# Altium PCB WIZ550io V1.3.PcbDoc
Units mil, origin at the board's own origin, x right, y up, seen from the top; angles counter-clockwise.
Board outline 2165.35 x 1023.62 mil, 4 copper layers (Top Layer, Internal Plane 1, Internal Plane 2, Bottom Layer); 65 components, 50 nets, 220 pads, 114 vias.
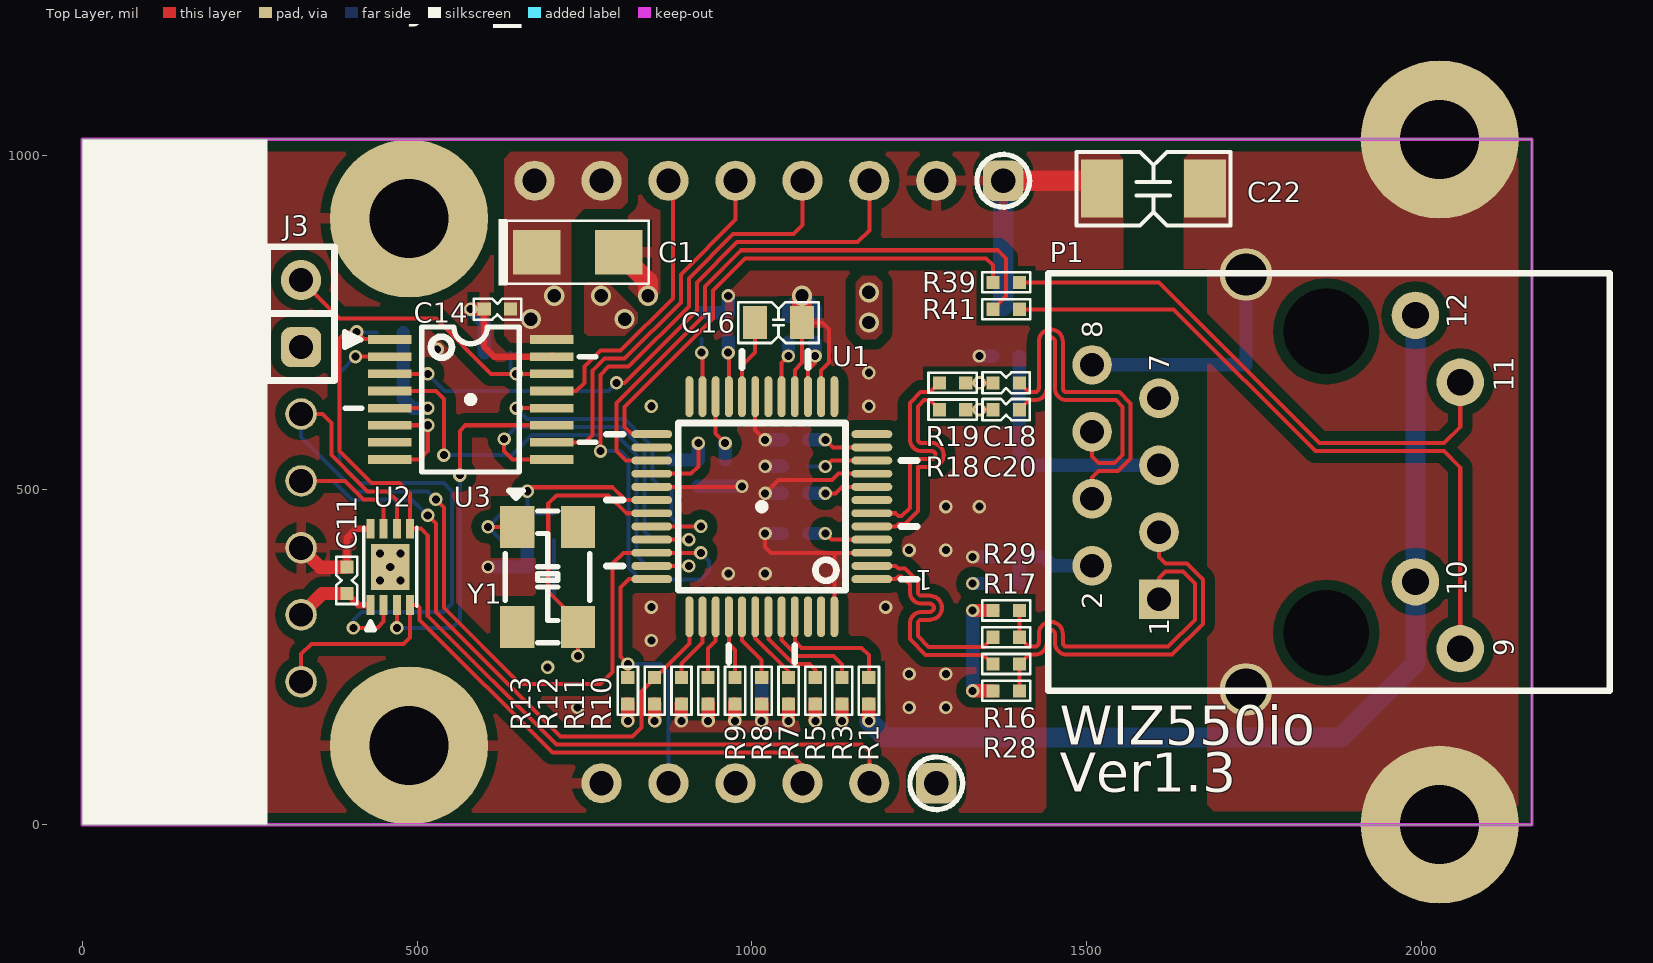
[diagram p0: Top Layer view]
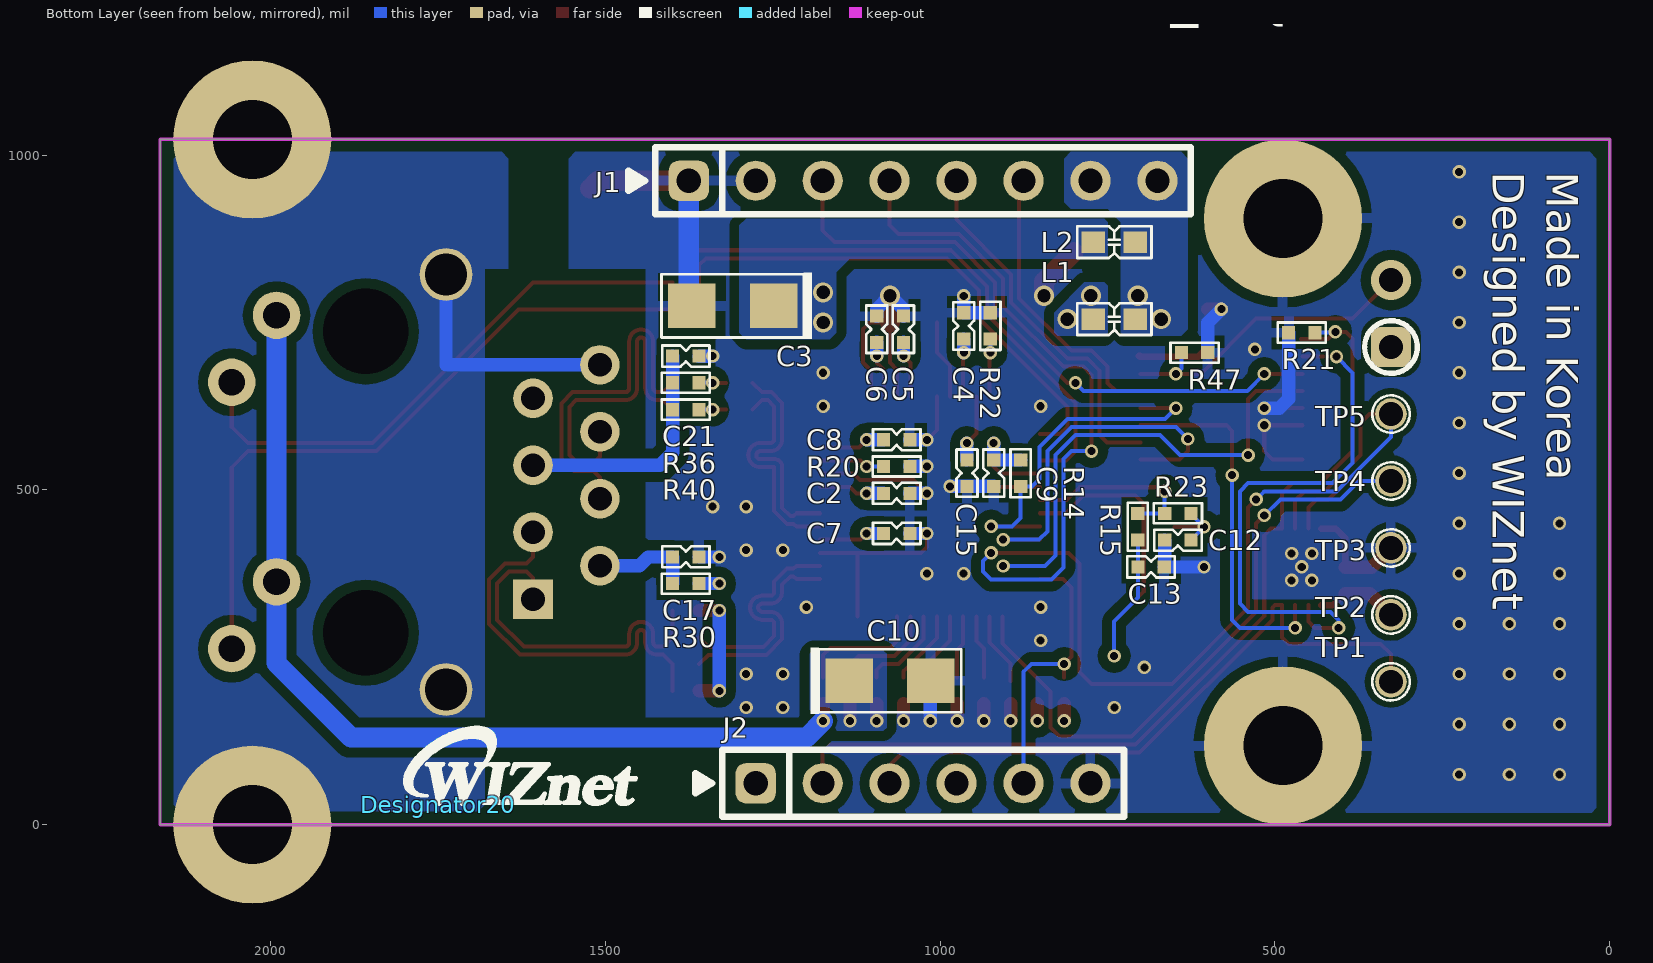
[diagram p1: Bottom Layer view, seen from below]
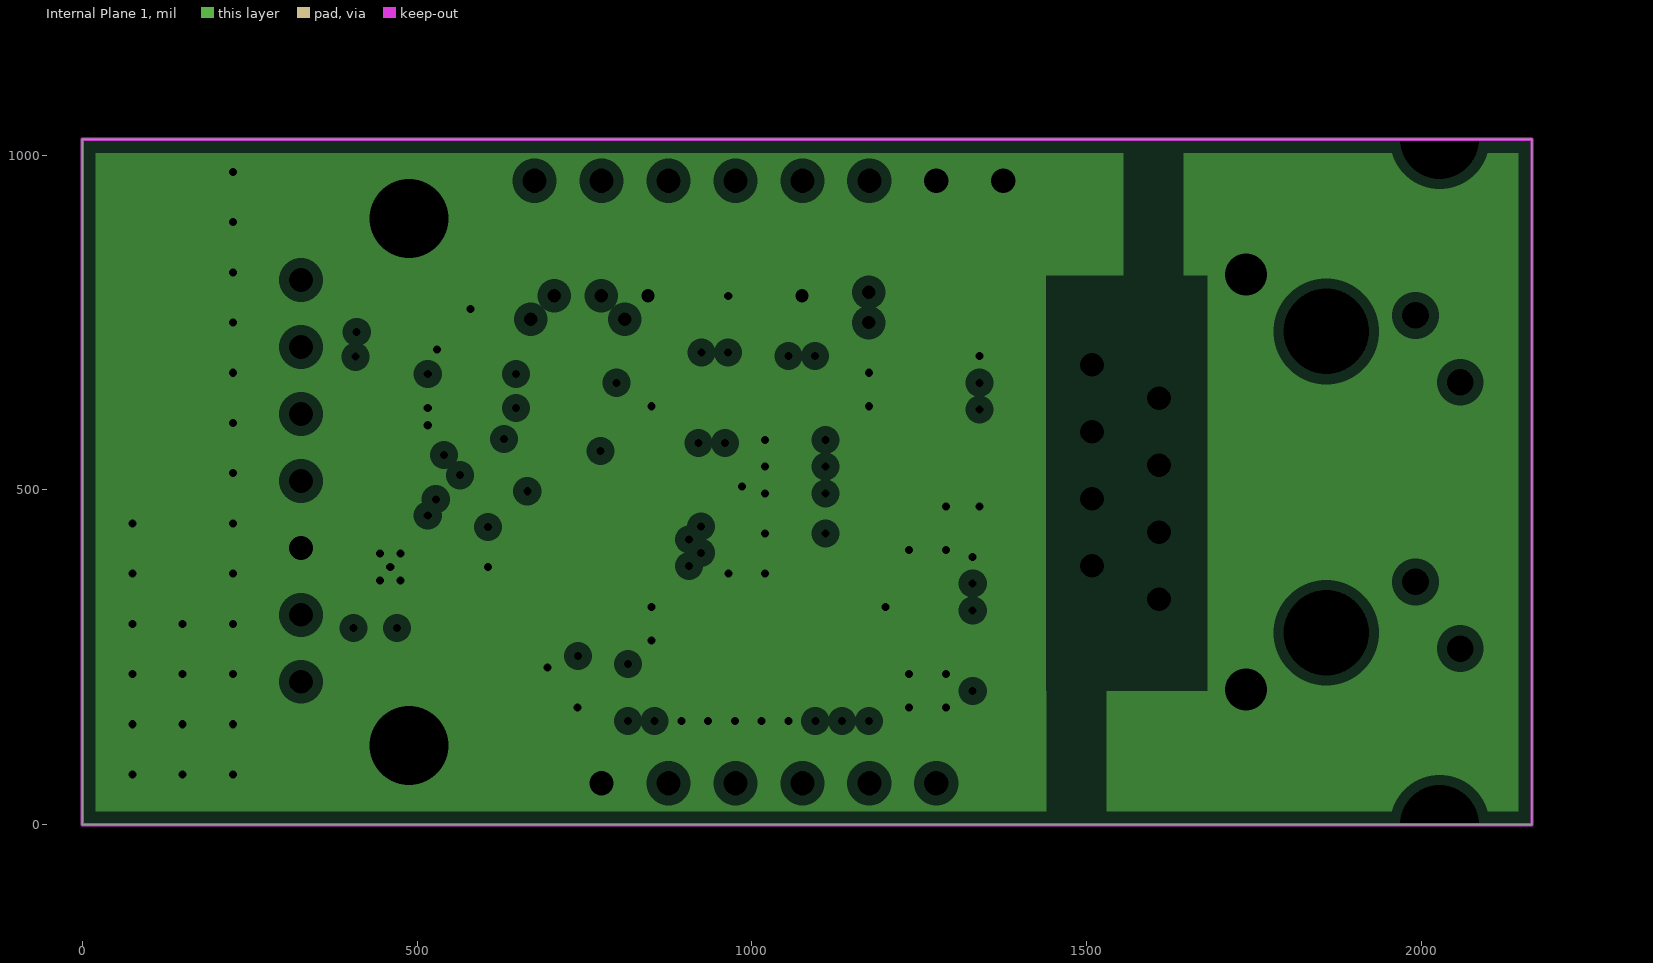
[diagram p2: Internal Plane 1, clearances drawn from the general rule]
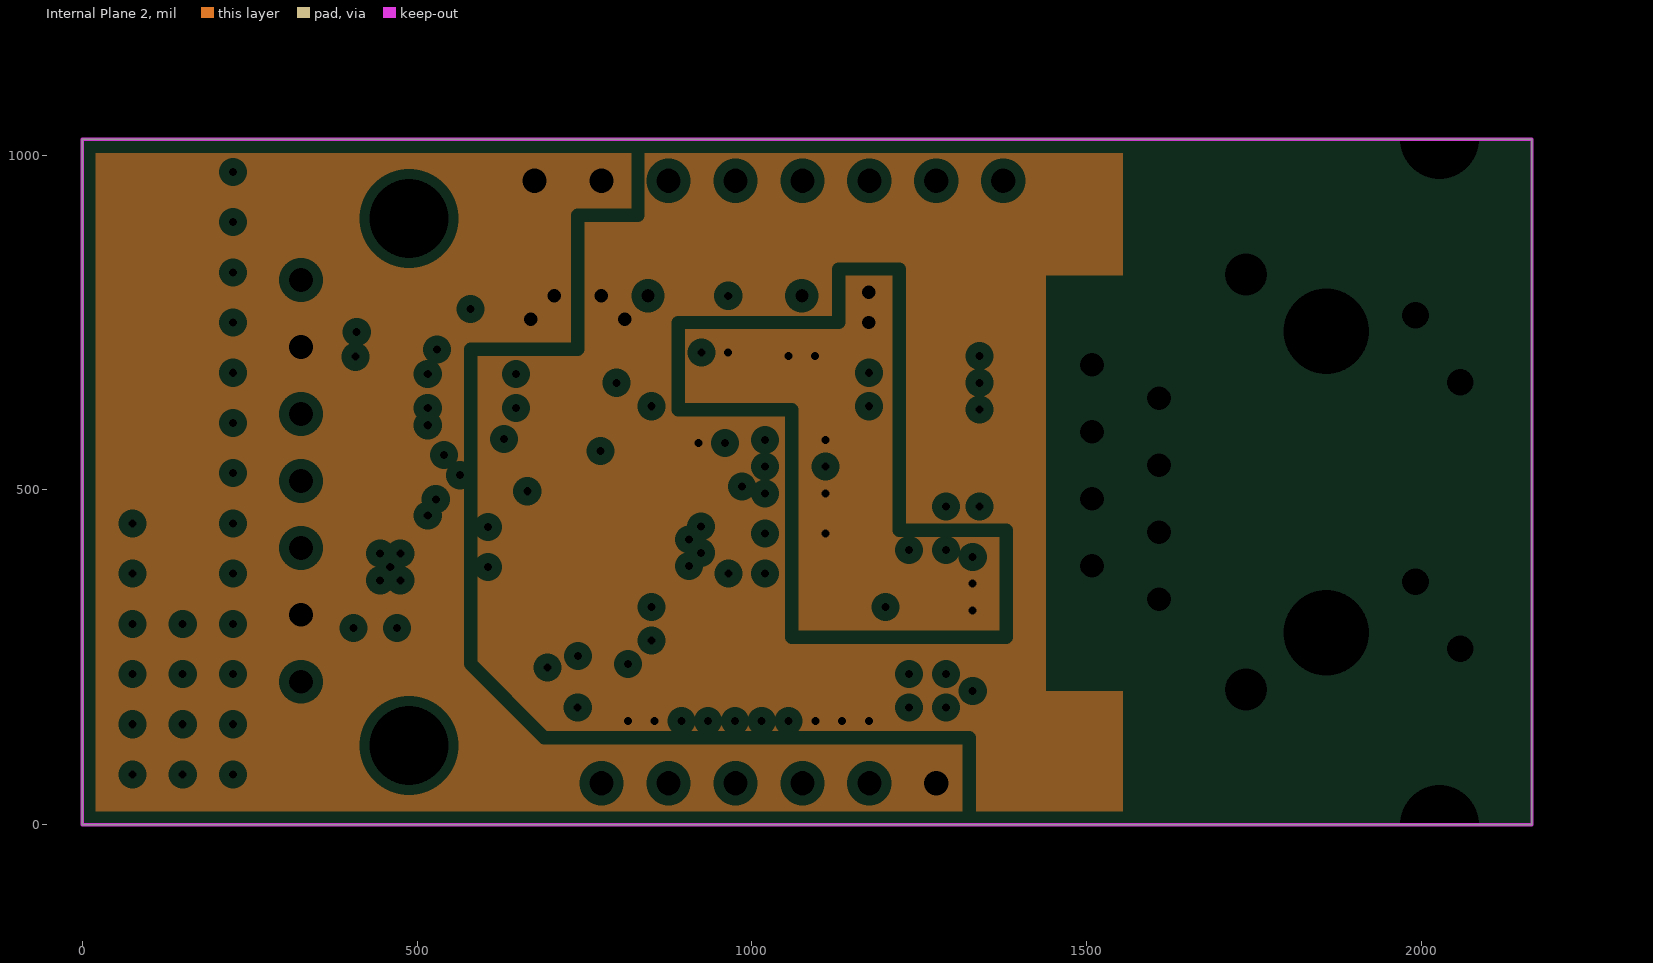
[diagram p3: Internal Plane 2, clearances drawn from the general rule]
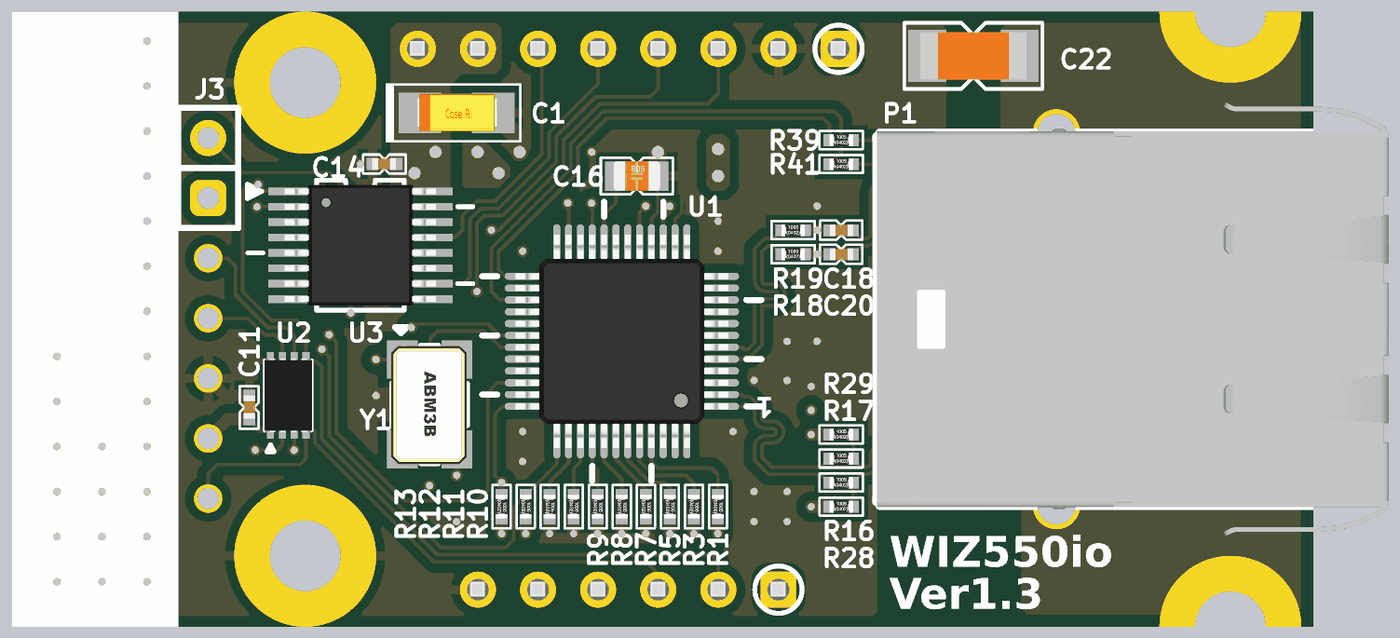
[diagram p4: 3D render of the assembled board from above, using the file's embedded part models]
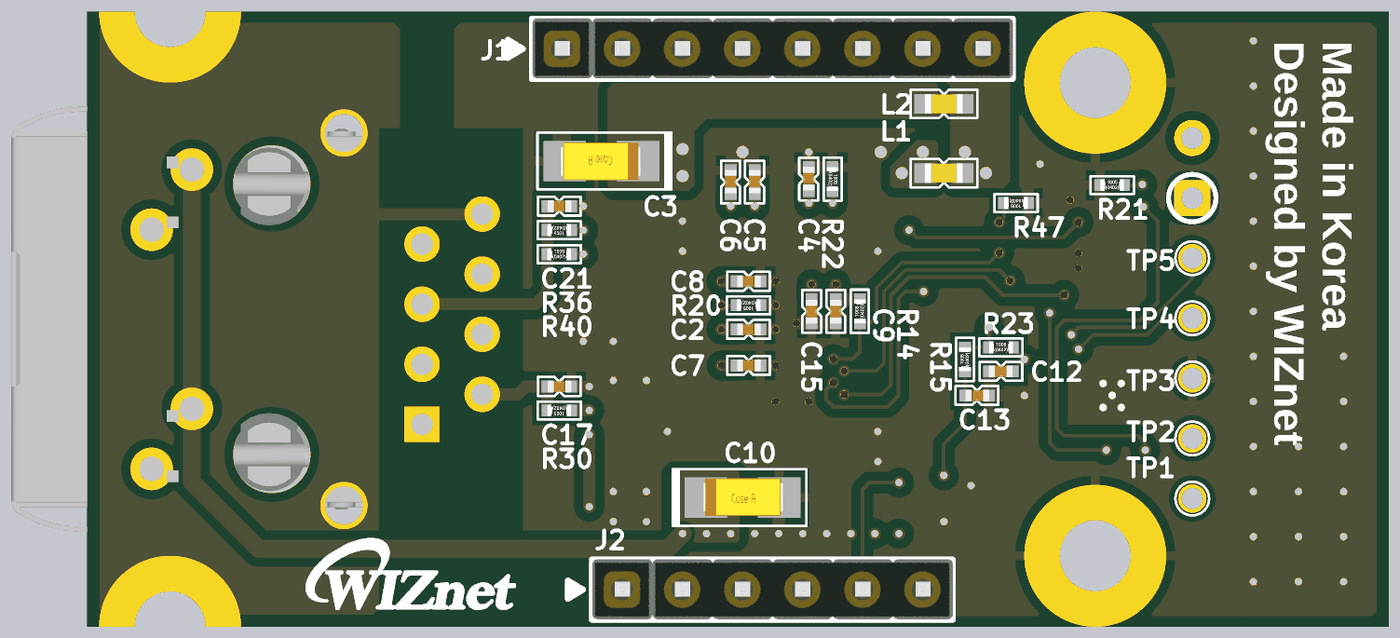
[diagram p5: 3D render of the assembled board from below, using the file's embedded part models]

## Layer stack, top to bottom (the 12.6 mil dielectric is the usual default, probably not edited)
Top Solder: solder mask 0.4, Solder Resist, Dk 3.5
Top Layer: signal copper 1.4
Dielectric1: core 12.6, FR-4, Dk 4.8
Internal Plane 1: plane copper 1.4
Dielectric5: prepreg 12.6, FR-4, Dk 4.8
Internal Plane 2: plane copper 1.4
Dielectric6: core 12.6, FR-4, Dk 4.8
Bottom Layer: signal copper 1.4
Bottom Solder: solder mask 0.4, Solder Resist, Dk 3.5

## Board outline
0,0 2165.35,0 2165.35,1023.62 0,1023.62

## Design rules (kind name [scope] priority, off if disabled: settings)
Clearance [All] p1: gap=6
DiffPairsRouting [All] p1: maxlimit=10 minlimit=5 mostfreqgap=6 toplayer_minwidth=15 toplayer_maxwidth=15 toplayer_prefwidth=15 bottomlayer_minwidth=15 bottomlayer_maxwidth=15 bottomlayer_prefwidth=15 maxuncoupledlength=500
HoleSize [All] p1: absolutevalues=TRUE maxlimit=160 minlimit=1 maxpercent=80.000 minpercent=20.000
PlaneClearance [All] p1: clearance=15
PlaneConnect [All] p1: planeconnectstyle=Direct reliefexpansion=20 reliefentries=4 reliefconductorwidth=10 reliefairgap=10
PolygonConnect PolygonConnect_2 [IsPad vs IsNamedPolygon('Top Layer-GND') Or  IsNamedPolygon('Bottom Layer-GND')] p1: connectstyle=Relief reliefconductorwidth=15 reliefentries=4 polygonreliefangle="90 Angle" airgapwidth=15
PolygonConnect PolygonConnect_1 [IsVia] p2: connectstyle=Direct reliefconductorwidth=10 reliefentries=4 polygonreliefangle="90 Angle" airgapwidth=10
PolygonConnect [All] p3: connectstyle=Direct reliefconductorwidth=10 reliefentries=4 polygonreliefangle="90 Angle" airgapwidth=10
RoutingVias [All] p1: holewidth=12 width=20 viastyle="Through Hole" minholewidth=12 minwidth=20 maxholewidth=20 maxwidth=30
SolderMaskExpansion [All] p1: expansion=0
Width [All] p1: maxlimit=100 minlimit=4 preferedwidth=10
26 further rules are at their usual default settings.

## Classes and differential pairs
differential pair RX2: +RX2_P -RX2_N
differential pair RX1: +RX1_P -RX1_N
differential pair RX: +RX_P -RX_N
differential pair TX1: +TX1_P -TX1_N
differential pair TX: +TX_P -TX_N

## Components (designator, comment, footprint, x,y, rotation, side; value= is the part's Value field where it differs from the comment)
C1 "10uF/16V" "CAP-A SIZE" 740,855 r0 top
C2 "0.1uF" CAP-0402 1065,495 r180 bottom
C3 "10uF/16V" "CAP-A SIZE" 1310,775 r0 bottom
C4 "0.1uF" CAP-0402 965,745 r90 bottom
C5 "0.1uF" CAP-0402 1055,740 r90 bottom
C6 "0.1uF" CAP-0402 1095,740 r90 bottom
C7 "0.1uF" CAP-0402 1065,435 r180 bottom
C8 "0.1uF" CAP-0402 1065,575 r180 bottom
C9 "0.1uF" CAP-0402 920,525 r270 bottom
C10 "10uF/16V" "CAP-A SIZE" 1075,215 r180 bottom
C11 "0.1uF" CAP-0402 395,365 r90 top
C12 "18pF" CAP-0402 645,425 r0 bottom
C13 "18pF" CAP-0402 685,385 r180 bottom
C14 "0.1uF" CAP-0402 620,770 r180 top
C15 "10nF" CAP-0402 960,525 r270 bottom
C16 "4.7uF" CAP-0805 1040,750 r0 top
C17 "22nF" CAP-0402 1380,400 r180 bottom
C18 "6.8nF" CAP-0402 1380,660 r0 top
C20 "6.8nF" CAP-0402 1380,620 r0 top
C21 "10nF" CAP-0402 1380,700 r180 bottom
C22 "1nF/2kV" CAP-1808 1600,950 r0 top
Designator20 "Comment" LOGO-WIZNET(SMALL) 1750,30 r180 bottom locked
J1 "HEADER 8" IDC-1X8 1375.59,961.81 r180 bottom locked
J2 "HEADER 6" IDC-1X6 1275.59,61.81 r180 bottom locked
J3 "HEADER 2" IDC-1X2 326.77,713.39 r90 top locked
L1 "HH-1M1608-121JT" CAP-0603 740,755 r180 bottom
L2 "HH-1M1608-121JT" CAP-0603 740,870 r180 bottom
P1 "J1B1211CCD" RJ45-J1B1211CCD 2165.35,511.81 r90 top locked
R1 "10K" RES-0402 1175,200 r270 top
R3 "10K" RES-0402 1135,200 r270 top
R5 "10K" RES-0402 1095,200 r270 top
R7 "10K" RES-0402 1055,200 r270 top
R8 "10K" RES-0402 1015,200 r270 top
R9 "10K" RES-0402 975,200 r270 top
R10 "10K" RES-0402 935,200 r270 top
R11 "10K" RES-0402 895,200 r270 top
R12 "10K" RES-0402 855,200 r270 top
R13 "10K" RES-0402 815,200 r270 top
R14 "10K" RES-0402 880,525 r90 bottom
R15 "1M" RES-0402 705,445 r90 bottom
R16 "33R" RES-0402 1380,240 r0 top
R17 "33R" RES-0402 1380,280 r0 top
R18 "33R" RES-0402 1300,620 r0 top
R19 "33R" RES-0402 1300,660 r0 top
R20 "12.4k 1%" RES-0402 1065,535 r0 bottom
R21 "10K" RES-0402 460,735 r180 bottom
R22 "10K" RES-0402 925,745 r270 bottom
R23 "0R" RES-0402 645,465 r180 bottom
R28 "49R9 1%" RES-0402 1380,200 r0 top
R29 "49R9 1%" RES-0402 1380,320 r0 top
R30 "10R 1%" RES-0402 1380,360 r0 bottom
R36 "49R9 1%" RES-0402 1380,660 r0 bottom
R39 "330R" RES-0402 1380,810 r0 top
R40 "49R9 1%" RES-0402 1380,620 r180 bottom
R41 "330R" RES-0402 1380,770 r0 top
R47 "10K" RES-0402 620,705 r0 bottom
TP1 "nMCLR_VPP" "TEST POINT" 326.77,213.39 r180 bottom locked
TP2 "3V3IN" "TEST POINT" 326.77,313.39 r180 bottom locked
TP3 "GND" "TEST POINT" 326.77,413.39 r180 bottom locked
TP4 "PDAT" "TEST POINT" 326.77,513.39 r180 bottom locked
TP5 "PCLK" "TEST POINT" 326.77,613.39 r180 bottom locked
U1 "W5500" W5500-LQFP48 1015,475 r180 top locked
U2 "PIC12F519" DFN08(0.5/2X3) 460,385 r90 top
U3 "MC74VHC157DTR2G" TSSOP16(0.65/6.4) 580,635 r0 top locked
Y1 "25MHz" OSC-KX53104 695,370 r270 top locked

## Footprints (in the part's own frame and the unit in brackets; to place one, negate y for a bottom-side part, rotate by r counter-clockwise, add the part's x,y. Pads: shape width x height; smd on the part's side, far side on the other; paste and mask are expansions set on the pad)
CAP-0402 [mm]
  rect 0.5x0.5 smd: 1(-0.5,-0.004) 2(0.5,-0.004)
  silkscreen extent -0.9,-0.4 0.9,0.4, body extent -0.48,-0.25 0.52,0.25, height 0.6
CAP-0603 [mm] "Ceramic CAP 0603(1608)"
  rect 0.89x0.82 smd: 1(-0.8,0) 2(0.8,0)
  silkscreen extent -1.41,-0.6 1.41,0.6, body extent -0.93,-0.41 0.93,0.41, height 0.81
CAP-0805 [mil]
  rect 36x49 smd: 1(-35,0)
  rect 35.43x49 smd: 2(35,0)
  silkscreen extent -60,-30 60,30, body extent -39,-24 40,25, height 31
CAP-1808 [mm] "Ceramic CAP 1808(4520)"
  rect 1.6x2.2 smd: 1(-1.95,0) 2(1.95,0)
  silkscreen extent -2.92,-1.4 2.92,1.4, body extent -2.25,-1.02 2.25,1.01, height 2
"CAP-A SIZE" [mm] "Tantal CAP A Size EIA/IECQ 3216"
  rect 1.8x1.7 smd: 1(-1.55,0) 2(1.55,0)
  silkscreen extent -3,-1.25 2.7,1.25, body extent -1.67,-0.78 1.72,0.82, height 1.75
DFN08(0.5/2X3) [mm]
  rect 0.75x0.3 smd: 1(-1.45,0.75) 2(-1.45,0.25) 3(-1.45,-0.25) 4(-1.45,-0.75) 5(1.45,-0.75) 6(1.45,-0.25) 7(1.45,0.25) 8(1.45,0.75)
  rect 1.75x1.45 smd: 9(0,0)
  silkscreen extent -2.38,-1 1.5,1, body extent -1.55,-1 1.55,1, height 0.75
IDC-1X2 [mil]
  rrect50% 60x60 hole 36: 1(0,0)
  round 60 hole 36: 2(100,0)
  silkscreen extent -50,-50 150,50
IDC-1X6 [mil] "6-Way 2.54 mm Male Header"
  rrect50% 60x60 hole 36: 1(0,0)
  round 60 hole 36: 2(100,0) 3(200,0) 4(300,0) 5(400,0) 6(500,0)
  silkscreen extent -90,-50 550,50, body extent -49,-49 551,51, height 336
IDC-1X8 [mil]
  rrect50% 60x60 hole 36: 1(0,0)
  round 60 hole 36: 2(100,0) 3(200,0) 4(300,0) 5(400,0) 6(500,0) 7(600,0) 8(700,0)
  silkscreen extent -90,-50 750,50, body extent -49,-49 751,51, height 336
LOGO-WIZNET(SMALL) [mil]
  silkscreen extent -50,0 296,115
OSC-KX53104 [mm]
  rect 1.6x1.3 smd: 1(-1.9,-1.15) 2(1.9,-1.15) 3(1.9,1.15) 4(-1.9,1.15)
  silkscreen extent -3.27,-1.6 2.5,1.6, body extent -2.47,-1.63 2.52,1.57, height 1.1
RES-0402 [mm]
  rect 0.5x0.5 smd: 1(-0.5,-0.004) 2(0.5,-0.004)
  silkscreen extent -0.91,-0.38 0.91,0.38, body extent -0.5,-0.25 0.5,0.25, height 0.35
RJ45-J1B1211CCD [mm]
  rect 1.5x1.5 hole 0.9: 1(-4.445,14.15)
  round 1.5 hole 0.9: 2(-3.175,16.69) 3(-1.905,14.15) 4(-0.635,16.69) 5(0.635,14.15) 6(1.905,16.69) 7(3.175,14.15) 8(4.445,16.69)
  round 1.8 hole 1.02: 9(-6.325,2.72) 10(-3.785,4.42) 11(3.785,2.72) 12(6.325,4.42)
  round 2 hole 1.6: 13(-7.875,10.85) 14(7.875,10.85)
  round 1.8 hole 3.25: ""(-5.715,7.8) ""(5.715,7.8)
  silkscreen extent -7.93,-2.95 7.93,18.35, body extent -9.16,-3.2 9.16,18.64, height 15.09
"TEST POINT" [mm] "TEST POINT"
  round 1.2 hole 0.9: 1(0,0)
  silkscreen extent -0.71,-0.71 0.71,0.71
TSSOP16(0.65/6.4) [mil]
  rect 65x13 smd: 1(-121.04,89.57) 2(-121.04,63.98) 3(-121.04,38.39) 4(-121.04,12.8) 5(-121.04,-12.8) 6(-121.04,-38.39) 7(-121.04,-63.98) 8(-121.04,-89.57) 9(121.04,-89.57) 10(121.04,-63.98) 11(121.04,-38.39) 12(121.04,-12.8) 13(121.04,12.8) 14(121.04,38.39) 15(121.04,63.98) 16(121.04,89.57)
  silkscreen extent -188,-108 187,108, body extent -126,-100 126,100, height 47
W5500-LQFP48 [mm]
  oval 1.55x0.3 smd: 1(-4.175,2.75) 2(-4.175,2.25) 3(-4.175,1.75) 4(-4.175,1.25) 5(-4.175,0.75) 6(-4.175,0.25) 7(-4.175,-0.25) 8(-4.175,-0.75) 9(-4.175,-1.25) 10(-4.175,-1.75) 11(-4.175,-2.25) 12(-4.175,-2.75) 25(4.175,-2.75) 26(4.175,-2.25) 27(4.175,-1.75) 28(4.175,-1.25) 29(4.175,-0.75) 30(4.175,-0.25) 31(4.175,0.25) 32(4.175,0.75) 33(4.175,1.25) 34(4.175,1.75) 35(4.175,2.25) 36(4.175,2.75)
  oval 0.3x1.55 smd: 13(-2.75,-4.175) 14(-2.25,-4.175) 15(-1.75,-4.175) 16(-1.25,-4.175) 17(-0.75,-4.175) 18(-0.25,-4.175) 19(0.25,-4.175) 20(0.75,-4.175) 21(1.25,-4.175) 22(1.75,-4.175) 23(2.25,-4.175) 24(2.75,-4.175) 37(2.75,4.175) 38(2.25,4.175) 39(1.75,4.175) 40(1.25,4.175) 41(0.75,4.175) 42(0.25,4.175) 43(-0.25,4.175) 44(-0.75,4.175) 45(-1.25,4.175) 46(-1.75,4.175) 47(-2.25,4.175) 48(-2.75,4.175)
  silkscreen extent -5.9,-5.9 5.9,5.9, body extent -4.5,-4.5 4.5,4.5, height 1.5

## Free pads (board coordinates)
  round 236.22 hole 118.11: ""(488.19,118.11) ""(488.19,905.51) ""(2027.56,0) ""(2027.56,1023.62)

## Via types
v1: diameter 20, hole 12, Top Layer to Bottom Layer, tented both sides, 106 vias
v2: diameter 30, hole 20, Top Layer to Bottom Layer, tented both sides, 8 vias

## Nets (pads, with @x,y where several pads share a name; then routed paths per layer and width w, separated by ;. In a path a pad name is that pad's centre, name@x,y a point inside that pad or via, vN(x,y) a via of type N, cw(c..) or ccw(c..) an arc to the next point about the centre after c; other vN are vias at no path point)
1V2O: C15.1 U1.22 | length 100.5
  Top Layer w6: U1.22 946.1,584.06 v1(960.16,570)
  Bottom Layer w20: C15.1 v1(960.16,570)
3V3A: C2.1 C3.1 C4.1 C5.1 C6.1 C7.1 C8.1 L2.1 R28.1 R29.1 R30.1 U1.4 U1.8 U1.11 U1.15 U1.17 U1.21 | length 764.4
  Top Layer w6: v1(964.68,705) 965.79,703.9 U1.21 ; U1.17 1044.53,689.84 v1(1054.68,700) ; U1.15 1083.9,678.9 1094.68,689.68 v1(1094.68,700) ; v1(1110,434.84) 1119.06,425.79 U1.4 ; v1(1110,494.84) 1124.84,494.84 1134.53,504.53 U1.8 ; v1(1110,574.84) 1121.26,563.58 U1.11
  Top Layer w20: v1(1330,199.84) R28.1 ; v1(1330,319.84) R29.1
  Bottom Layer w20: v1@964.84,705 C4.1 ; v1@1054.84,700 C5.1 ; C7.1 v1(1110,434.84) ; C2.1 v1(1110,494.84) ; C8.1 v1(1110,574.84) ; v1@1094.84,700 C6.1 ; v1(1330,199.84) v1(1330,319.84) ; v1(1330,360.16) R30.1
  other v2: 1175,750 1175,795
3V3D: C9.1 C10.1 L1.1 P1.10 P1.12 R1.2 R3.2 R5.2 R12.2 R13.2 R14.2 U1.28 | length 1693.6
  Top Layer w6: U1.28 909.21,524.21 920.16,535.16 v1(920.16,570)
  Top Layer w20: v1(814.84,155) R13.2 ; v1(854.84,155) R12.2 ; v1(1094.84,155) R5.2 ; v1(1134.84,155) R3.2 ; v1(1174.84,155) R1.2
  Bottom Layer w20: R14.2 C9.1 v1(920.16,570)
  Bottom Layer w30: v1(1174.84,155) 1199.84,130 1880,130 1991.34,241.34 P1.10 P1.12
  other v2: 810,755 775,790
3V3IN: C1.1 C11.1 C14.1 J1.7 J1.8 J2.1 J3.1 L1.2 L2.2 TP2.1 U2.1 U3.16 | length 124.1
  Top Layer w10: C11.1 412.56,327.91 U2.1
  Top Layer w20: TP2.1 358.7,345.31 C11.1
  other v2: 670,755 705,790
ACTLED: R41.1 U1.27 | length 920.8
  Top Layer w6: U1.27 812.1,543.9 798,558 798,630 930,762 930,804 984,858 1368,858 1380,846 1380,789.53 R41.1
CGND: C22.2 P1.8 P1.13 P1.14 pad.@2027.56,0 pad.@2027.56,1023.62 | length 365
  Bottom Layer w20: P1.8 1738.19,686.81 P1.14
EXRES1: R20.2 U1.10 | length 98.4
  Top Layer w6: v1(1110,535) 1118.9,543.9 U1.10
  Bottom Layer w6: R20.2 v1@1110,535.16
GND: C1.2 C2.2 C3.2 C4.2 C5.2 C6.2 C7.2 C8.2 C9.2 C10.2 C11.2 C12.2 C13.2 C14.2 C15.2 C16.2 C17.2 C21.2 C22.1 J1.1 J1.2 J2.6 pad.@488.19,118.11 pad.@488.19,905.51 R7.2 R8.2 R9.2 R10.2 R11.2 R20.1 R21.1 R22.1 R47.1 TP3.1 U1.3 U1.9 U1.14 U1.16 U1.19 U1.29 U1.48 U2.8 U2.9 U3.5 U3.6 U3.8 U3.15 | length 2810.7
  Top Layer w6: U3.8 503.43,545.43 516,558 v1(516,596.61) U3.6 ; U3.5 v1(516,622.2) ; U1.29 v1@984.68,504.53 ; U1.19 1005.16,589.69 v1(1020,574.84) ; v1(1020,434.84) 1020,415 1028.9,406.1 U1.3 ; v1(1020,494.84) 1040.16,515 1120,515 1129.21,524.21 U1.9 ; U1.16 1064.21,679.21 1075,690 C16.2 1105,750 1115,740 1115,690 1103.58,678.58 U1.14 ; U1.48 1123.27,404.83
  Top Layer w10: C11.2 395.16,428.16 409.09,442.09 U2.8 ; C14.2 600.32,713.68 615.02,698.98 U3.15 ; U3.15@701.04,699.98 U3.15@703.04,699.98
  Top Layer w20: TP3.1 355.47,384.69 C11.2 ; v1@580,770.16 C14.2 ; v1(894.84,155) R11.2 ; v1(934.84,155) R10.2 ; v1(974.84,155) R9.2 ; v1(1014.84,155) R8.2 ; v1(1054.84,155) R7.2
  Top Layer w30: C1.2 845,811.02 v2(845,790) ; C16.2 v2(1075,790) ; J1.1 1511.42,961.81 C22.1
  Bottom Layer w20: R21.1 479.68,636.32 493.8,622.2 v1(516,622.2) ; v1(580,770) 600.32,749.68 R47.1 ; v1(606,384.84) C13.2 664.68,385.47 C12.2 ; C9.2 C15.2 v1(985.47,505.31) ; R22.1 C4.2 v1(964.84,790) ; C10.2 1014.84,214.13 v1(1014.84,155) ; v1(1020,434.84) C7.2 ; v1(1020,494.84) C2.2 ; v1(1020,535.16) R20.1 ; v1(1020,574.84) C8.2 ; C5.2 1054.84,769.84 v2(1075,790) 1094.84,770.16 C6.2 ; v1(1330,399.84) C17.2 ; v1@1340,699.84 C21.2
  Bottom Layer w30: C3.2 1375.59,775 J1.1
  other v1: 75,75 150,75 225,75 75,150 150,150 225,150 740,175 1235,175 1290,175 75,225 150,225 225,225 1235,225 1290,225 695,235 850,275 75,300 150,300 225,300 850,325 1200,325 445,365 475,365 75,375 225,375 965,375 1020,375 460,385 445,405 475,405 1235,410 1290,410 75,450 225,450 1290,475 1340,475 225,525 225,600 850,625 1175,625 225,675 1175,675 1340,700 530,710 225,750 225,825 225,900 225,975
ICSPCLK: J1.4 TP5.1 U1.34 U2.6 | length 2288.6
  Top Layer w6: TP5.1 358.61,613.39 372,600 372,552 413.42,510.58 426,498 456,498 469.84,484.16 U2.6 ; v1(528,486) 540,474 540,324 654,210 774,210 792,228 792,390 808.1,406.1 U1.34 v1(924,406.1) ; v1(774,558) 774,672 786,684 816,684 906,774 906,816 972,882 1062,882 1075.59,895.59 J1.4
  Bottom Layer w6: TP5.1 326.77,579.23 408,498 516,498 v1(528,486) ; v1(774,558) 804,558 816,546 816,384 834,366 924,366 936,378 936,394.1 v1(924,406.1)
ICSPDAT: R12.1 TP4.1 U1.37 U2.7 | length 1115.8
  Top Layer w6: TP4.1 392.61,513.39 420,486 438,486 450.16,473.84 U2.7 ; v1(516,462) 528,450 528,318 714,132 822,132 835,145 835,199 906.73,270.73 U1.37
  Bottom Layer w6: TP4.1 374.61,513.39 402,486 492,486 v1(516,462)
INTN: J2.5 R13.1 U1.36 | length 422.9
  Top Layer w6: R13.1 v1(814.84,240) 804,250.84 804,354 816.73,366.73 U1.36
  Bottom Layer w6: v1(814.84,240) 864,240 875.59,228.41 J2.5
LINKLED: R39.1 U1.25 | length 772.1
  Top Layer w6: U1.25 820.73,583.27 810,594 810,624 942,756 942,798 990,846 1350,846 1360.32,835.68 R39.1
MOSI: U1.35 U3.4 | length 771.6
  Top Layer w6: U3.4 528.2,647.8 540,636 v1(540,552) ; U1.35 v1(906,386.42)
  Bottom Layer w6: v1(540,552) 642,552 672,582 798,582 828,552 828,402 843.58,386.42 v1@905,386.42
MOSI_A: U2.2 U3.2 | length 815.9
  Top Layer w6: v1(405,294) 441,294 450.16,303.16 U2.2 ; v1(408,698.98) U3.2
  Bottom Layer w6: v1(405,294) 405,306 417,318 540,318 552,330 552,498 540,510 414,510 384,540 384,674.98 v1(408,698.98)
MOSI_B: J1.3 U3.3 | length 925.2
  Top Layer w6: U3.3 v1(516,673.39) ; v1(798,660) 810,660 918,768 918,810 978,870 1158,870 1175.59,887.59 J1.3
  Bottom Layer w6: v1(516,673.39) 541.39,648 786,648 v1(798,660)
N3248382: C21.1 P1.5 R36.2 R40.1 | length 360.2
  Bottom Layer w20: C21.1 R36.2 R40.1 1399.68,556.32 1419.19,536.81 P1.5
N3248458: C17.1 P1.2 R30.2 | length 153.7
  Bottom Layer w20: R30.2 C17.1 1436.16,399.84 1449.19,386.81 P1.2
N3271839: R22.2 U1.23 | length 86.5
  Top Layer w6: v1(925.16,705) 926.42,703.74 U1.23
  Bottom Layer w6: v1(925.16,705) R22.2
N3303068: P1.11 R39.2 | length 834.5
  Top Layer w6: R39.2 1608.16,809.84 1848,570 2034,570 2058.27,594.27 P1.11
N3303104: P1.9 R41.2 | length 1027.3
  Top Layer w6: R41.2 1630.16,769.84 1842,558 2034,558 2058.27,533.73 P1.9
N3553124: C12.1 R23.2 Y1.1 | length 99.4
  Top Layer w6: v1(606,444.8) Y1.1
  Bottom Layer w6: C12.1 625.32,425.49 v1(606,444.8) 625.32,464.12 R23.2
NMCLR_VPP: J2.3 TP1.1 U2.4 | length 985.2
  Top Layer w6: TP1.1 326.77,254.77 342,270 480,270 489.53,279.53 U2.4 500.09,327.91 504,324 504,306 702,108 1056,108 1075.59,88.41 J2.3
NRDY: J2.2 R21.2 U2.5 U3.1 | length 1409.8
  Top Layer w6: U3.1@460.96,725.57 420.43,725.57 v1(409.9,736.1) 394.1,736.1 384,726 384,558 432,510 474,510 489.53,494.47 U2.5 505.91,442.09 516,432 516,312 708,120 1164,120 1175.59,108.41 J2.2
  Bottom Layer w6: v1(409.9,736.1) 411.16,734.84 R21.2
PMODE0: R1.1 U1.45 | length 189.2
  Top Layer w6: U1.45 1064.21,274.31 1074.53,264 1164,264 1174.84,253.16 R1.1
PMODE1: R3.1 U1.44 | length 160
  Top Layer w6: U1.44 1044.53,275.47 1068,252 1122,252 1134.84,239.16 R3.1
PMODE2: R5.1 U1.43 | length 134
  Top Layer w6: U1.43 1024.84,277.16 1062,240 1086,240 1094.84,231.16 R5.1
RSVD1: R11.1 U1.38 | length 109
  Top Layer w6: R11.1@894.84,214.69 R11.1 894.84,240.84 926.42,272.42 U1.38
RSVD2: R10.1 U1.39 | length 95.6
  Top Layer w6: R10.1 934.84,262.84 946.1,274.1 U1.39
RSVD3: R9.1 U1.40 | length 94.7
  Top Layer w6: U1.40 965.79,270.21 974.84,261.16 R9.1
RSVD4: R8.1 U1.41 | length 103.1
  Top Layer w6: U1.41 985.47,275.37 1014.84,246 R8.1
RSVD5: R7.1 U1.42 | length 111.5
  Top Layer w6: U1.42 1005.16,278.84 1054.84,229.16 R7.1
RX1_N: C20.1 R18.2 R40.2 | length 60.8
  Top Layer w6: R18.2 C20.1
  Bottom Layer w6: v1@1340.16,619.84 R40.2
  other v1: 1340,620
RX1_P: C18.1 R19.2 R36.1 | length 60.8
  Top Layer w6: R19.2 C18.1
  Bottom Layer w6: v1@1340.16,660.16 R36.1
  other v1: 1340,660
RX2_N: C20.2 P1.6 | length 494.8
  Top Layer w6: C20.2 1413.84,634 1422.68,634 ccw(c1422.68,652) 1440.68,652 1440.68,721.64 cw(c1446.68,721.64) 1452.68,721.64 1452.68,652 ccw(c1470.68,652) 1470.68,634 1544,634 1554,624 1554,552 1542,540 1518,540 1508.27,549.73 P1.6
RX2_P: C18.2 P1.4 | length 528.8
  Top Layer w6: C18.2 1413.53,646 1422.68,646 ccw(c1422.68,652) 1428.68,652 1428.68,721.64 cw(c1446.68,721.64) 1464.68,721.64 1464.68,652 ccw(c1470.68,652) 1470.68,646 1548.97,646 1566,628.97 1566,547.03 1546.97,528 1518,528 1508.27,518.27 P1.4
RX_N: R18.1 U1.5 | length 336
  Top Layer w6: U1.5 1215,445.47 1218.84,449.31 1228.97,449.31 1248,468.34 1248,534 1268.76,534 ccw(c1268.76,552) 1286.76,552 ccw(c1268.76,552) 1268.76,570 1254,570 cw(c1254,576) 1248,576 1248,624.68 1257.32,634 1266.16,634 R18.1
RX_P: R19.1 U1.6 | length 335.8
  Top Layer w6: U1.6 1215,465.16 1218.84,461.31 1224,461.31 1236,473.31 1236,534 cw(c1248,534) 1248,546 1268.76,546 ccw(c1268.76,552) 1274.76,552 ccw(c1268.76,552) 1268.76,558 1254,558 cw(c1254,576) 1236,576 1236,629.66 1252.34,646 1266.47,646 R19.1
SCLK: U1.33 U3.9 | length 572
  Top Layer w6: v1(630,576) 630,558 642.57,545.43 U3.9 ; U1.33 v1(906,425.79)
  Bottom Layer w6: v1(630,576) 648,594 804,594 840,558 840,438 852.21,425.79 v1@905,425.79
SCLK_A: U2.3 U3.11 | length 555.7
  Top Layer w6: v1(469.84,294) U2.3 ; v1(564,522) 564,588 572.61,596.61 U3.11
  Bottom Layer w6: v1(469.84,294) 552,294 564,306 v1(564,522)
SCLK_B: J1.5 U3.10 | length 551.4
  Top Layer w6: U3.10 751.02,571.02 762,582 762,678 780,696 810,696 894,780 894,822 975.59,903.59 J1.5
SCSN: R14.1 U1.32 U3.12 | length 532.4
  Top Layer w6: v1(648,622.2) U3.12 ; U1.32 v1(924,445.47)
  Bottom Layer w6: v1(648,622.2) 664.2,606 810,606 852,564 852,516 862.68,505.31 R14.1 879.84,458.16 892.53,445.47 v1(924,445.47) v1@925,445.47
SCSN_A: J3.2 R47.2 U3.14 | length 467.5
  Top Layer w6: J3.2 384.16,756 528,756 610.61,673.39 v1(648,673.39) U3.14
  Bottom Layer w6: R47.2 639.68,681.7 v1(648,673.39)
SCSN_B: J1.6 U3.13 | length 430.7
  Top Layer w6: U3.13 737.8,647.8 750,660 750,684 774,708 804,708 882,786 882,955.4 J1.6
TOCAP: C16.1 U1.20 | length 118.7
  Top Layer w6: U1.20 985.47,685.47 1005,705 C16.1
TX1_N: P1.3 R16.2 R28.2 | length 575.2
  Top Layer w6: R28.2 R16.2 1413.84,254 1422.68,254 ccw(c1422.68,272) 1440.68,272 1440.68,284.88 cw(c1446.68,284.88) 1452.68,284.88 1452.68,272 ccw(c1470.68,272) 1470.68,254 1628,254 1674,300 1674,366 1650,390 1618,390 1608.27,399.73 P1.3
TX1_P: P1.1 R17.2 R29.2 | length 528.4
  Top Layer w6: R29.2 R17.2 1413.53,266 1422.68,266 ccw(c1422.68,272) 1428.68,272 1428.68,284.88 cw(c1446.68,284.88) 1464.68,284.88 1464.68,272 ccw(c1470.68,272) 1470.68,266 1622,266 1662,306 1662,360 1644,378 1618,378 1608.27,368.27 P1.1
TX_N: R16.1 U1.1 | length 335.9
  Top Layer w6: U1.1 1215,366.73 1218.84,370.57 1224,370.57 1236,358.57 1236,348 ccw(c1254,348) 1254,330 1266,330 cw(c1266,324) 1272,324 cw(c1266,324) 1266,318 1254,318 ccw(c1254,300) 1236,300 1236,277.03 1259.34,253.69 1346.47,253.69 R16.1
TX_P: R17.1 U1.2 | length 336
  Top Layer w6: U1.2 1215,386.42 1218.84,382.57 1228.97,382.57 1248,363.55 1248,348 ccw(c1254,348) 1254,342 1266,342 cw(c1266,324) 1284,324 cw(c1266,324) 1266,306 1254,306 ccw(c1254,300) 1248,300 1248,282 1264.32,265.69 1346.16,265.69 R17.1
XI: R15.2 R23.1 U1.30 | length 269.7
  Top Layer w6: v1(664.68,498) 670.68,504 792,504 811.16,484.84 U1.30
  Bottom Layer w6: v1(664.68,498) R23.1 664.84,464.69 R15.2
XO: C13.1 R15.1 U1.31 Y1.3 | length 605.1
  Top Layer w6: v1(740.28,252) Y1.3 740.28,303.72 696,348 696,480 708,492 786,492 812.84,465.16 U1.31
  Bottom Layer w6: R15.1 704.84,339.16 740.28,303.72 v1(740.28,252)
pads on no net: J2.4 P1. P1.7 U1.7 U1.12 U1.13 U1.18 U1.24 U1.26 U1.46 U1.47 U3.7 Y1.2 Y1.4

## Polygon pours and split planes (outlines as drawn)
GND on Bottom Layer "Top Layer-GND" (solid, remove dead copper, pour order 17): 1555,995 1545,1005 30,1005 20,995 20,25 30,15 1430,15 1440,25 1440,830 1555,830
CGND on Bottom Layer "Top Layer-NET" (solid, remove dead copper, pour order 23): 1645,995 1655,1005 2135,1005 2145,995 2145,30 2135,20 1690,20 1680,30 1680,830 1645,830
3V3D on Bottom Layer "Top Layer-No Net" (solid, pour order 24): 1085,140 1080,145 1080,160 1080,255 1085,260 1105,260 1190,260 1195,255 1195,145 1190,140
3V3IN on Bottom Layer "Top Layer-No Net" (solid, pour order 15): 730,735 725,730 640,730 630,740 630,995 640,1005 805,1005 815,995 815,930 805,920 750,920 730,900
3V3A on Bottom Layer "Top Layer-No Net" (solid, pour order 18): 750,900 755,905 1290,905 1300,895 1300,735 1290,725 1165,725 1155,735 1155,825 1135,845 755,845 750,850
3V3D on Bottom Layer "Top Layer-No Net" (solid, pour order 14): 775,730 755,730 750,735 750,750 750,805 755,810 785,810 830,765 830,755 830,735 825,730
GND on Top Layer "Top Layer-NET" (solid, remove dead copper, pour order 21): 1555,858.98 1555,995 1545,1005 1470,1005 1470,860
GND on Top Layer "Top Layer-GND" (solid, remove dead copper, pour order 16): 1555,995 1545,1005 30,1005 20,995 20,25 30,15 1430,15 1440,25 1440,830 1555,830
CGND on Top Layer "Top Layer-NET" (solid, pour order 22): 1645,995 1655,1005 2135,1005 2145,995 2145,30 2135,20 1690,20 1680,30 1680,830 1645,830
3V3IN on Top Layer "Top Layer-No Net" (solid, pour order 13): 640,720 630,730 630,995 640,1005 805,1005 815,995 815,930 805,920 750,920 730,900 730,725 725,720
3V3D on Top Layer "Top Layer-No Net" (solid, pour order 20): 755,730 750,735 750,805 755,810 785,810 815,780 830,765 830,755 830,750 815,735 810,730 755,730
3V3A on Top Layer "Top Layer-No Net" (solid, pour order 19): 1165,725 1155,735 1155,810 1165,820 1185,820 1195,810 1195,735 1185,725
CGND on Internal Plane 1 (split plane): 2145.26,20.1 1529.78,20.1 1530.1,25 1530.1,200 1680,200 1680,820 1645.1,820 1645.1,1000 1644.87,1003.53 2145.26,1003.53
GND on Internal Plane 1 (split plane): 1554.9,1000 1554.9,820.1 1485,820.1 1483.53,820 1440,820 1440,776.47 1439.9,775 1439.9,25 1440.22,20.1 20.1,20.1 20.1,1003.53 1555.13,1003.53
3V3A on Internal Plane 2 (split plane): 1209.91,440 1210.26,437.39 1211.26,434.96 1212.87,432.87 1214.96,431.26 1217.39,430.26 1220,429.91 1369.91,429.91 1369.91,290.09 1070.09,290.09 1070.09,620 1069.74,622.61 1068.74,625.04 1067.13,627.13 1065.04,628.74 1062.61,629.74 1060,630.09 900.09,630.09 900.09,739.91 1130,739.91 1132.61,740.26 1135.04,741.26 1137.13,742.87 1138.74,744.96 1139.74,747.39 1140.09,750 1140.09,819.91 1209.91,819.91
3V3D on Internal Plane 2 (split plane): 1555,820 1440,820 1440,200 1555,200 1555,20.1 1335.09,20.1 1335.09,130 1334.74,132.61 1333.74,135.04 1332.13,137.13 1330.04,138.74 1327.61,139.74 1325,140.09 694.18,140.09 590.09,244.18 590.09,699.91 740,699.91 742.61,700.26 745.04,701.26 747.13,702.87 748.74,704.96 749.74,707.39 750.09,710 750.09,899.91 830,899.91 832.61,900.26 835.04,901.26 837.13,902.87 838.74,904.96 839.74,907.39 840.09,910 840.09,1003.53 1555,1003.53
3V3IN on Internal Plane 2 (split plane): 819.91,920.09 740,920.09 737.39,919.74 734.96,918.74 732.87,917.13 731.26,915.04 730.26,912.61 729.91,910 729.91,720.09 580,720.09 577.39,719.74 574.96,718.74 572.87,717.13 571.26,715.04 570.26,712.61 569.91,710 569.91,240 570.26,237.39 571.26,234.96 572.87,232.87 682.87,122.87 684.96,121.26 687.39,120.26 690,119.91 1314.91,119.91 1314.91,20.1 20.1,20.1 20.1,1003.53 819.91,1003.53

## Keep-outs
Keep-Out Layer:
  the board outline again, w5
  text ".Layer_Name" at 360,1210 h60

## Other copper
Top Layer:
  pour cut-out: 1440,200 1680,200 1680,830 1440,830
  text ".Layer_Name" at 360,1210 h60
Bottom Layer:
  pour cut-out: 1440,830 1680,830 1680,200 1440,200
  text ".Layer_Name" at 360,1210 h60
Internal Plane 1 (plane layer: these items are gaps in the copper):
  rectangle: 1440,200 1680,820
  lines w90: 1485,25 1485,775 1600,775 1600,1000
  text "GND" at 360,1210 h60
Internal Plane 2 (plane layer: these items are gaps in the copper):
  rectangle: 1440,200 1680,820
  pour cut-out: 1555,1023.62 1555,820 1440,820 1440,200 1555,200 1555,0 2165.35,0 2165.35,1023.62
  lines w20: 830,1023.62 830,910 740,910 740,710 580,710 580,240 690,130 1325,130 1325,0 ; 890,620 890,750 1130,750 1130,830 1220,830 1220,440 1380,440 1380,280 1060,280 1060,620 890,620
  text "POWER" at 360,1210 h60
  text "3V3D" at 760,860 h30
  text "3V3IN" at 395,775 h30
  text "3V3A" at 1080,300 h30

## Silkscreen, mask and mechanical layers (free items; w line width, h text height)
Top Overlay:
  rectangle: 0,0 276.77,1023.62
  text ".Layer_Name" at 360,1210 h60
  text "WIZ550io" at 1460,100 h100
  text "Ver1.3" at 1460,30 h100
Bottom Overlay:
  text ".Layer_Name" at 360,1210 h60
  text "Made in Korea" at 110,975 h80 r90
  text "Designed by WIZnet" at 190,975 h80 r90
Top Paste:
  text ".Layer_Name" at 360,1210 h60
Bottom Paste:
  text ".Layer_Name" at 360,1210 h60
Top Solder:
  text ".Layer_Name" at 360,1210 h60
Bottom Solder:
  text ".Layer_Name" at 360,1210 h60
Drill Guide:
  text ".Layer_Name" at 360,1210 h60
Mechanical 2:
  lines w5: 2405,640 3435,640 ; 2405,750 3435,750 ; 0,0 2165.35,0 2165.35,1023.62 0,1023.62 0,0 ; 2352,193 ccw(c2380,193) 2380,165 3450,165 ccw(c3450,193) 3478,193 3478,950 ccw(c3450,950) 3450,978 2380,978 ccw(c2380,950) 2352,950 2352,193
  text "BOARD NAME : WIZ550io" at -10,1650 h60
  text "VERSION : V1.3" at -10,1540 h60
  text "SIZE : 55mmX26mmX1.6T" at -10,1430 h60
  text "GERBER DATE : 2017.07.10" at -10,1320 h60
  text "LAYER :" at -10,1210 h60
  text "Layer Stack Up Detail for:" at 2410,895 h40
  text "WIZ550io V1.3.PcbDoc" at 2405,800 h50
  text "Layer Name : 4L  1.6T" at 2410,675 h40
  text "Top Layer" at 2405,530 h60
  text "GND" at 2405,420 h60
  text "POWER" at 2405,315 h60
  text "Bottom Layer" at 2405,215 h60
  text "KS-TECH artwork" at 2350,0 h200
Drill Drawing:
  text ".Layer_Name" at 360,1210 h60
  text ".Legend" at 1330,1210 h40

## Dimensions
0,0 to 2027.56,0 on Mechanical 3
0,1023.62 to 1375.59,961.81 on Mechanical 3
0,1023.62 to 488.19,905.51 on Mechanical 3
2200,961.81 to 2165.35,1023.62 on Mechanical 3
2165.35,0 to 2281.5,199.8 on Mechanical 3
1275.59,61.81 to 1375.59,961.81 on Mechanical 3
488.19,118.11 to 488.19,905.51 on Mechanical 3
0,0 to 1275.59,61.81 on Mechanical 3
0,0 to 0,1023.62 on Mechanical 3
0,0 to 2165.35,0 on Mechanical 3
